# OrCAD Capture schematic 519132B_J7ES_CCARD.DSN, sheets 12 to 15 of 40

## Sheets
12 12. SOC MCU FLASH: size C
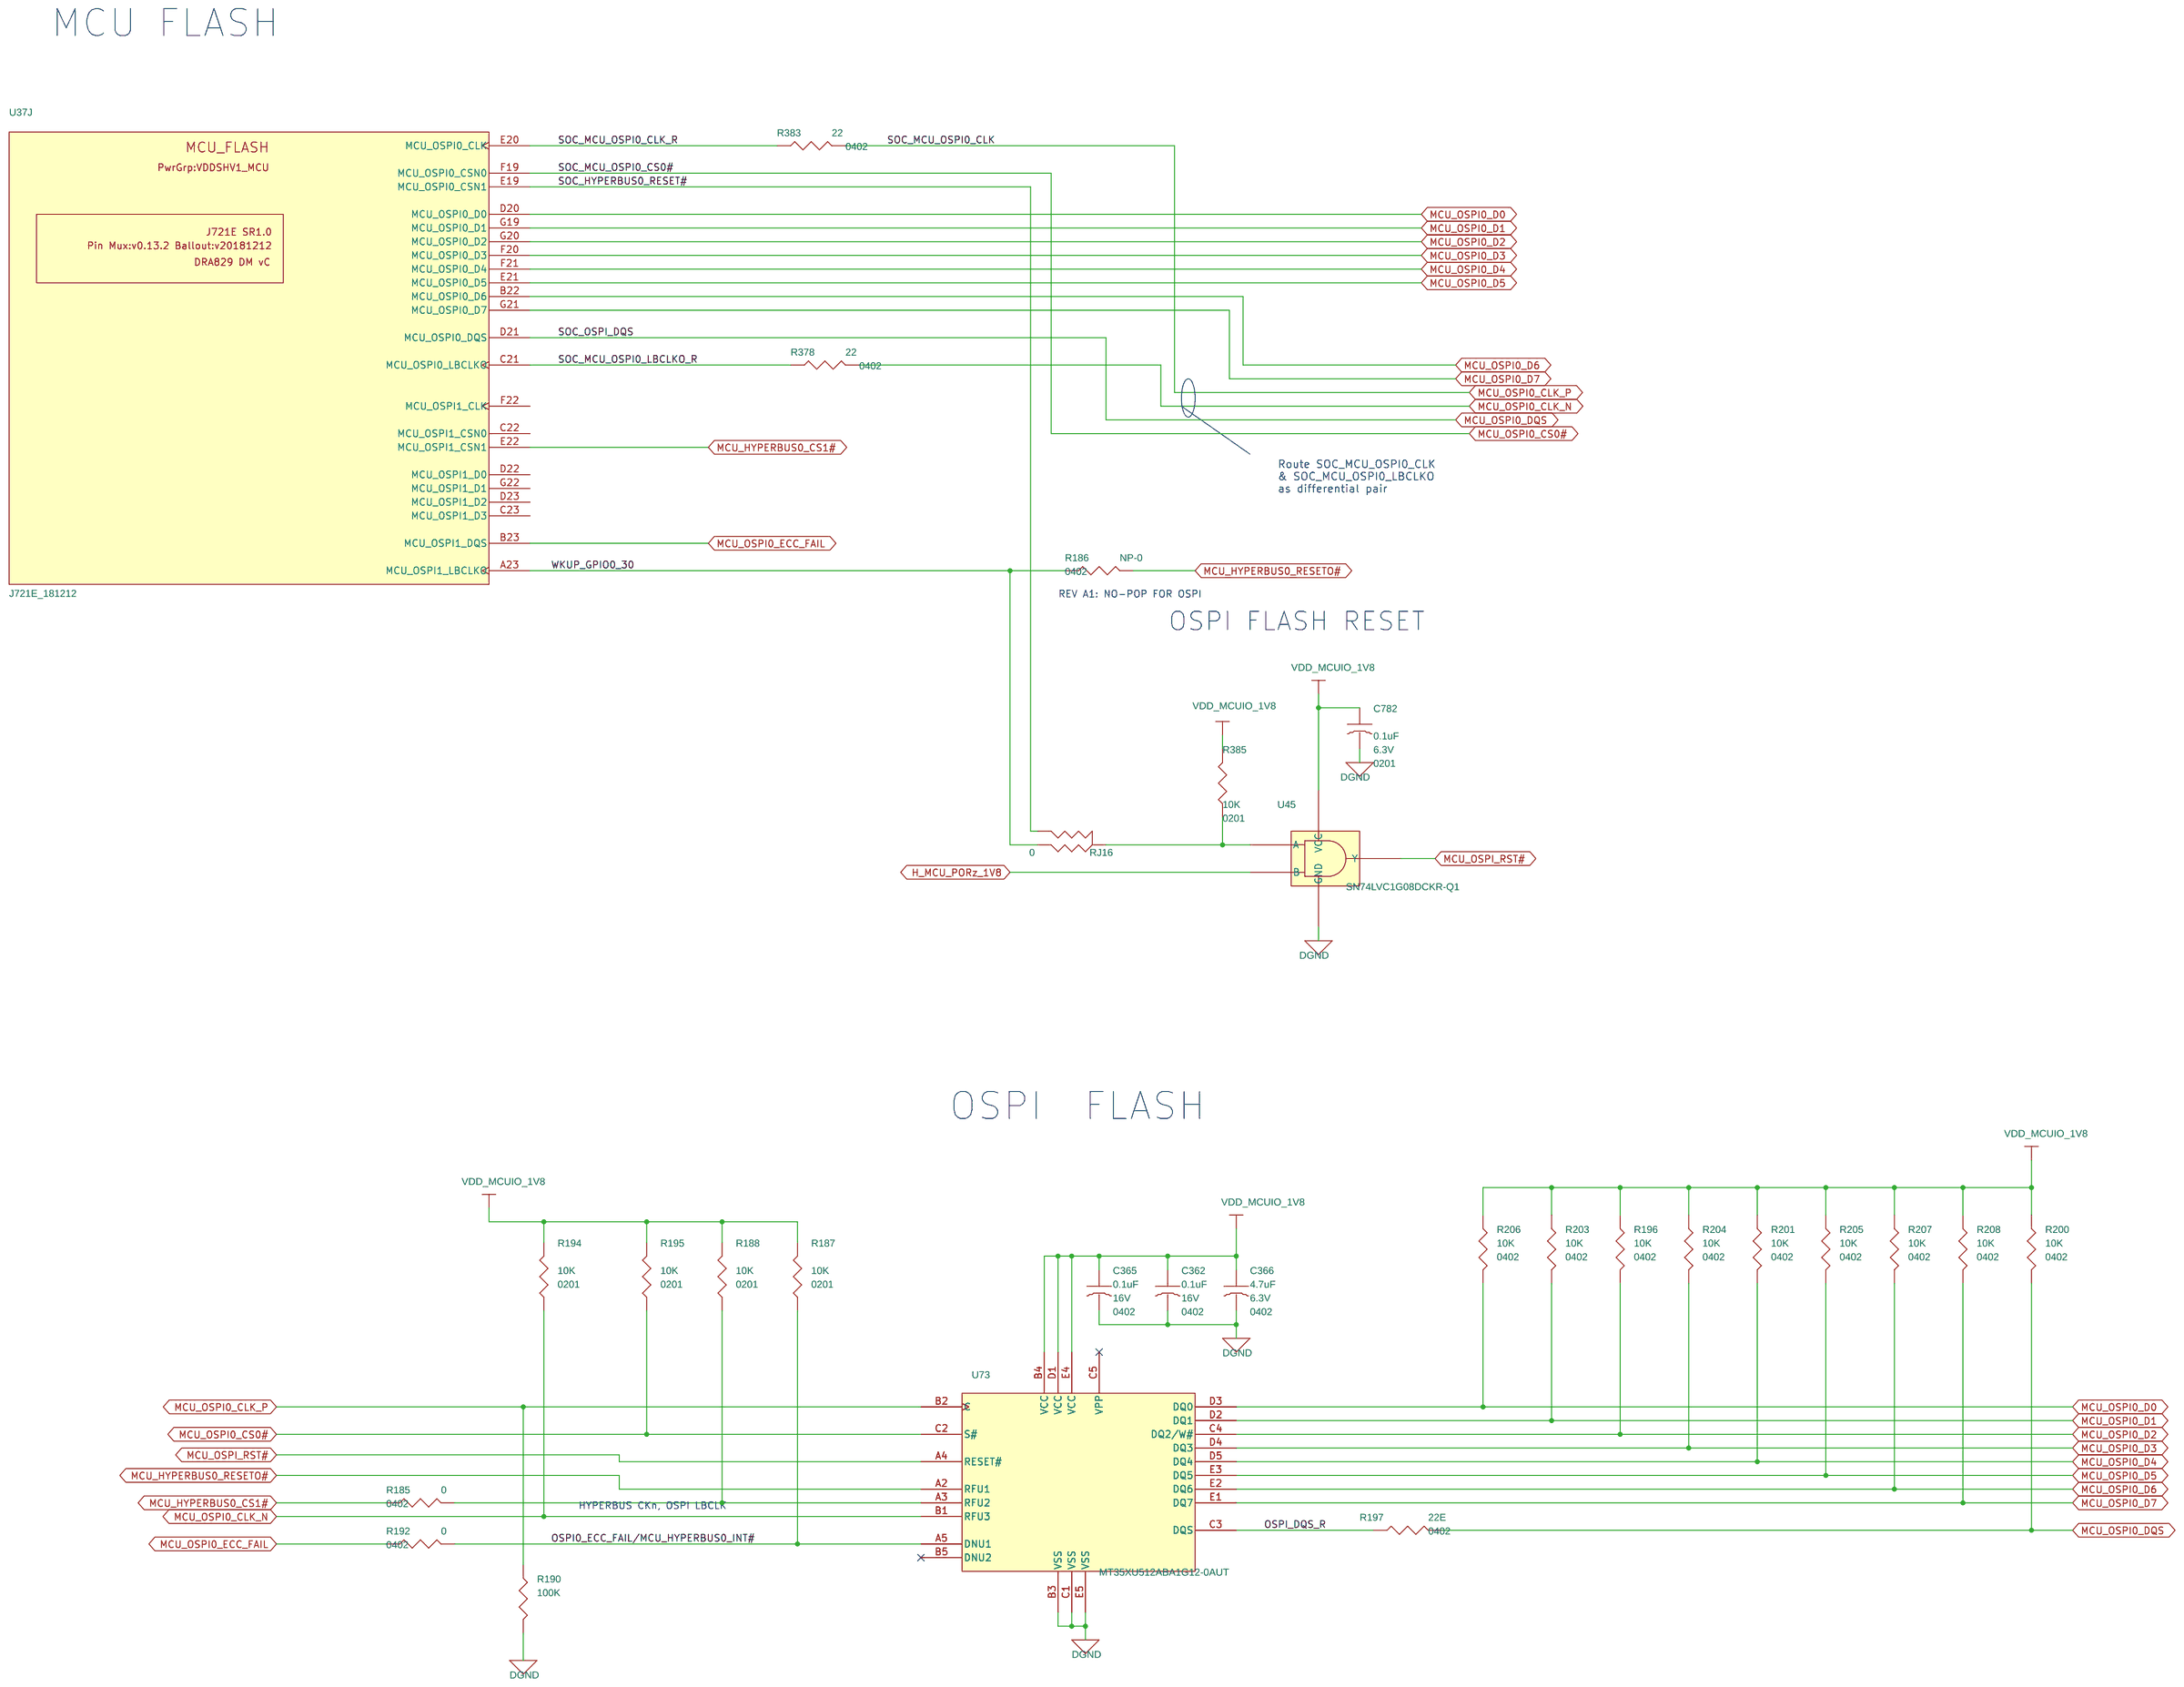
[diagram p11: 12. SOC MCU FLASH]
13 13. SOC RGMII, ADC: size C; rev: A
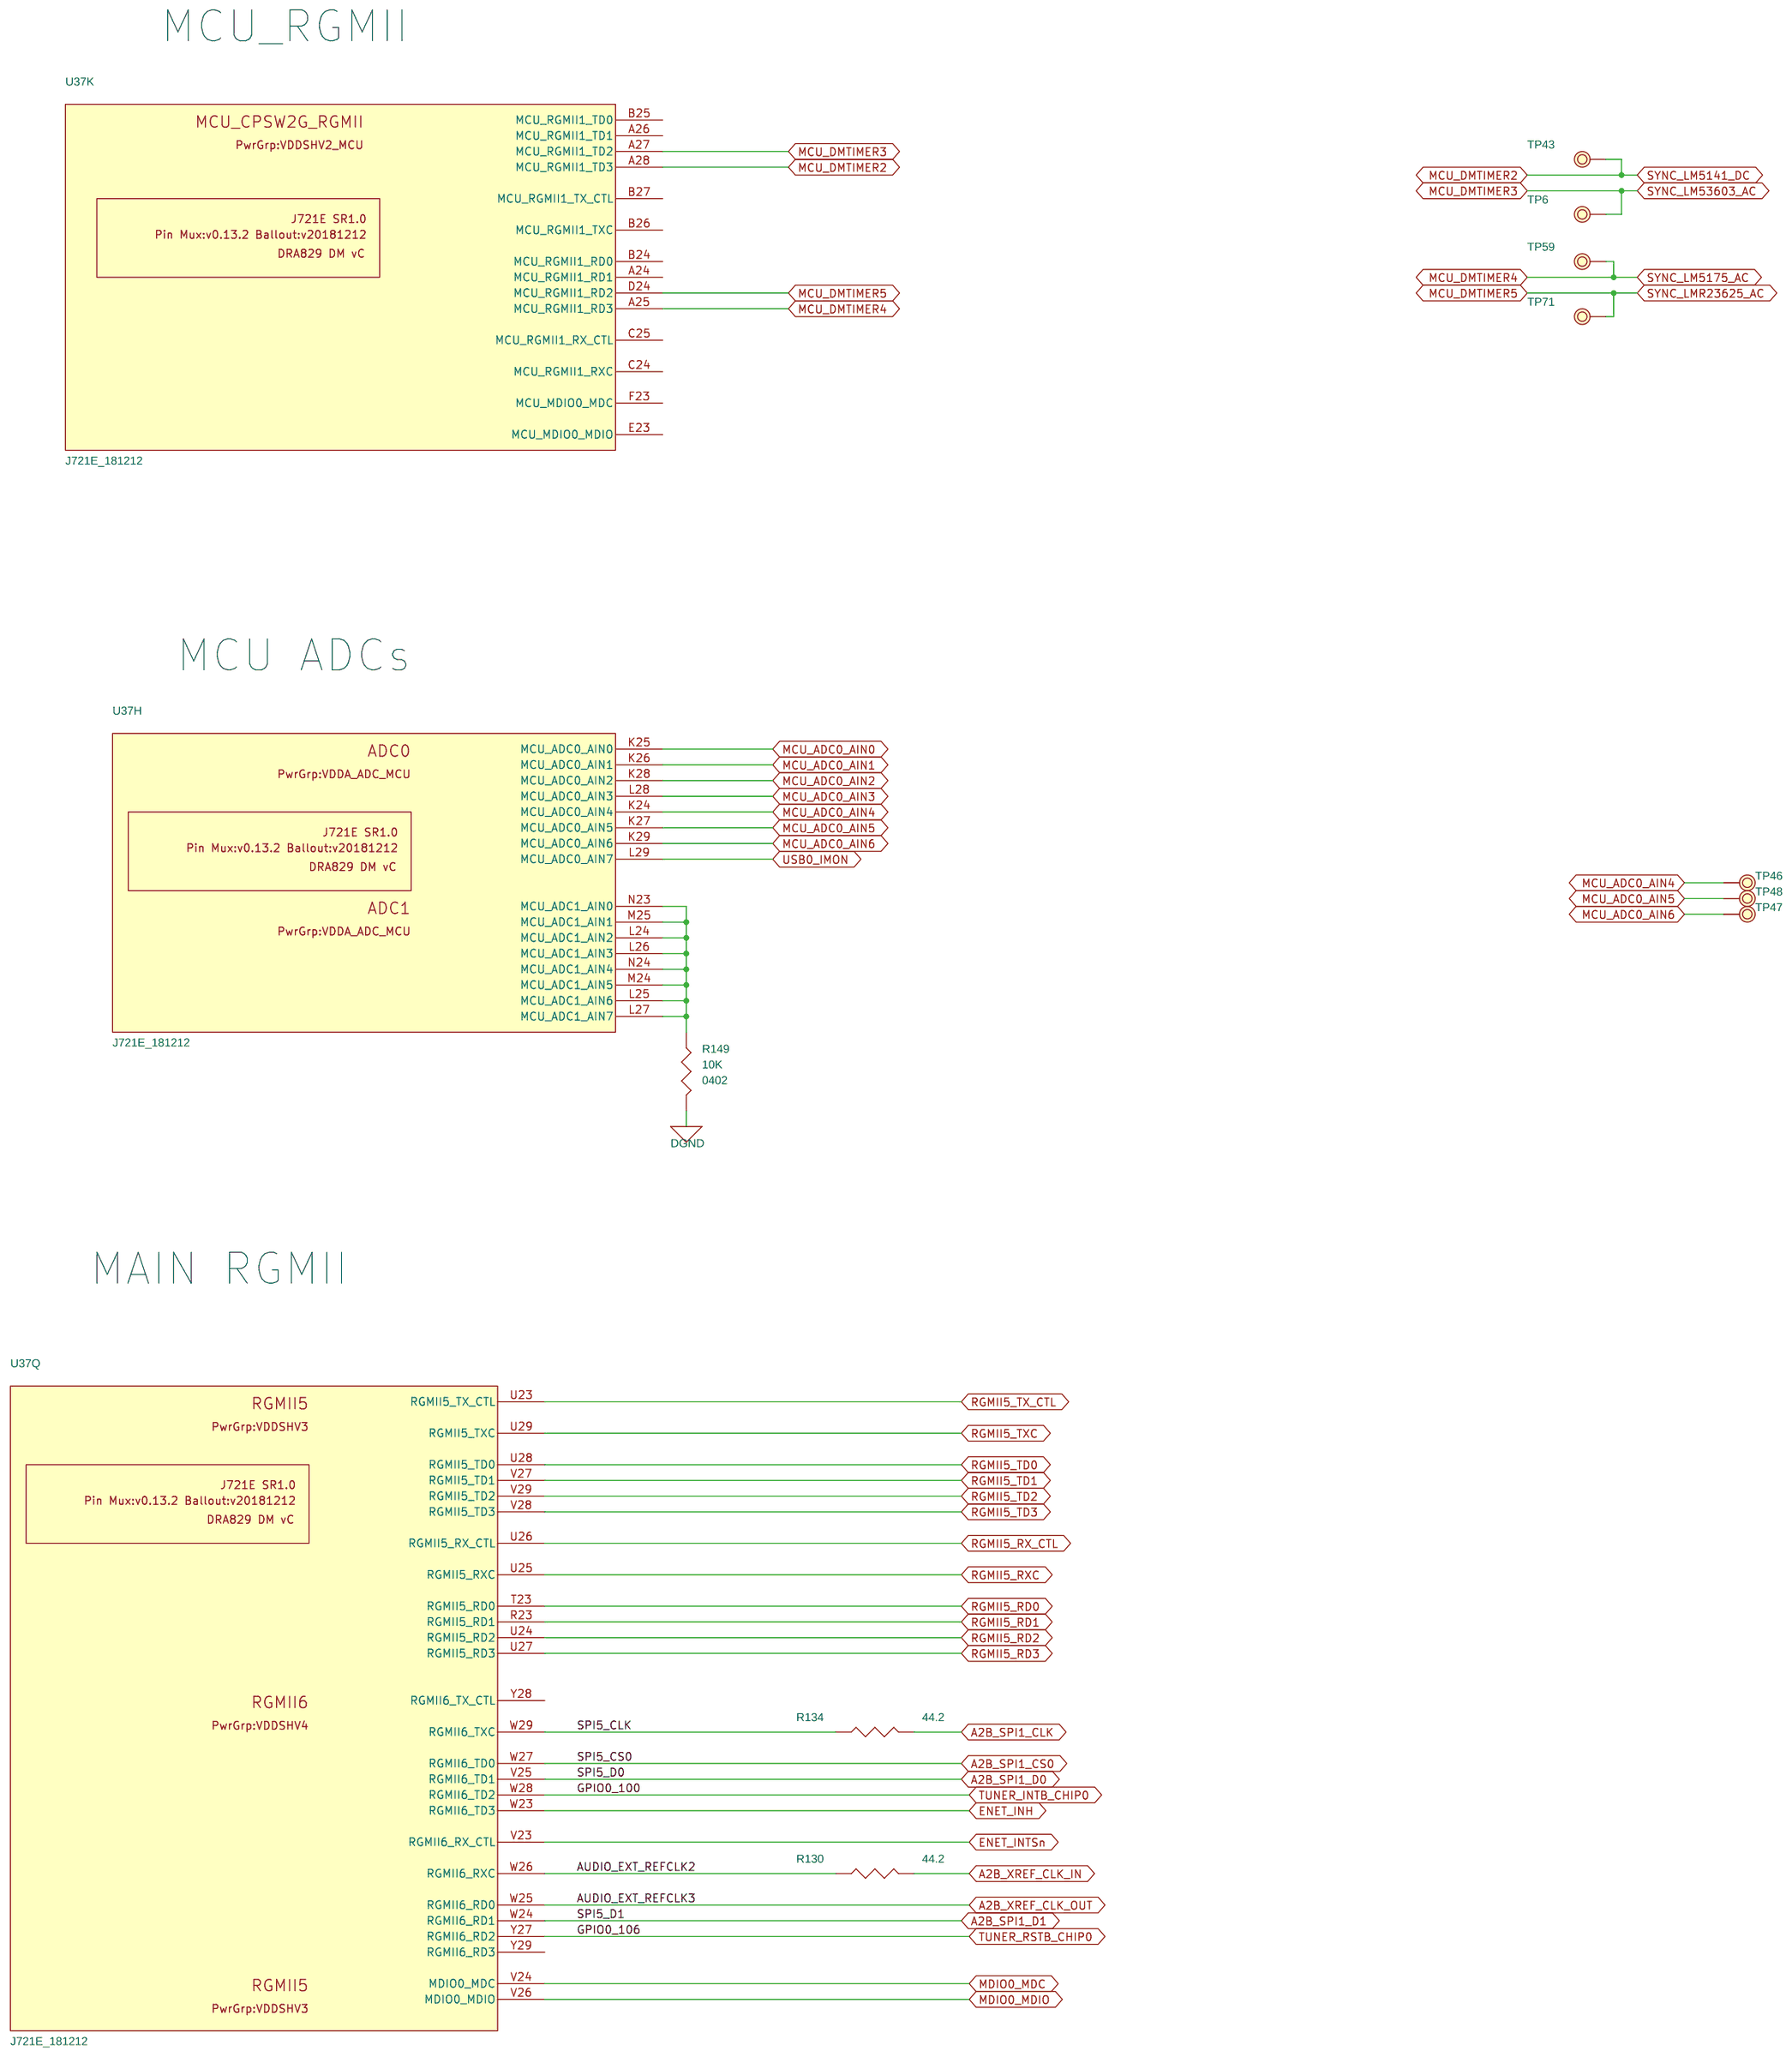
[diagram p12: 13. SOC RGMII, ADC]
14 14. SOC MCU & MAIN GEN IO, OSC: size C; rev: A
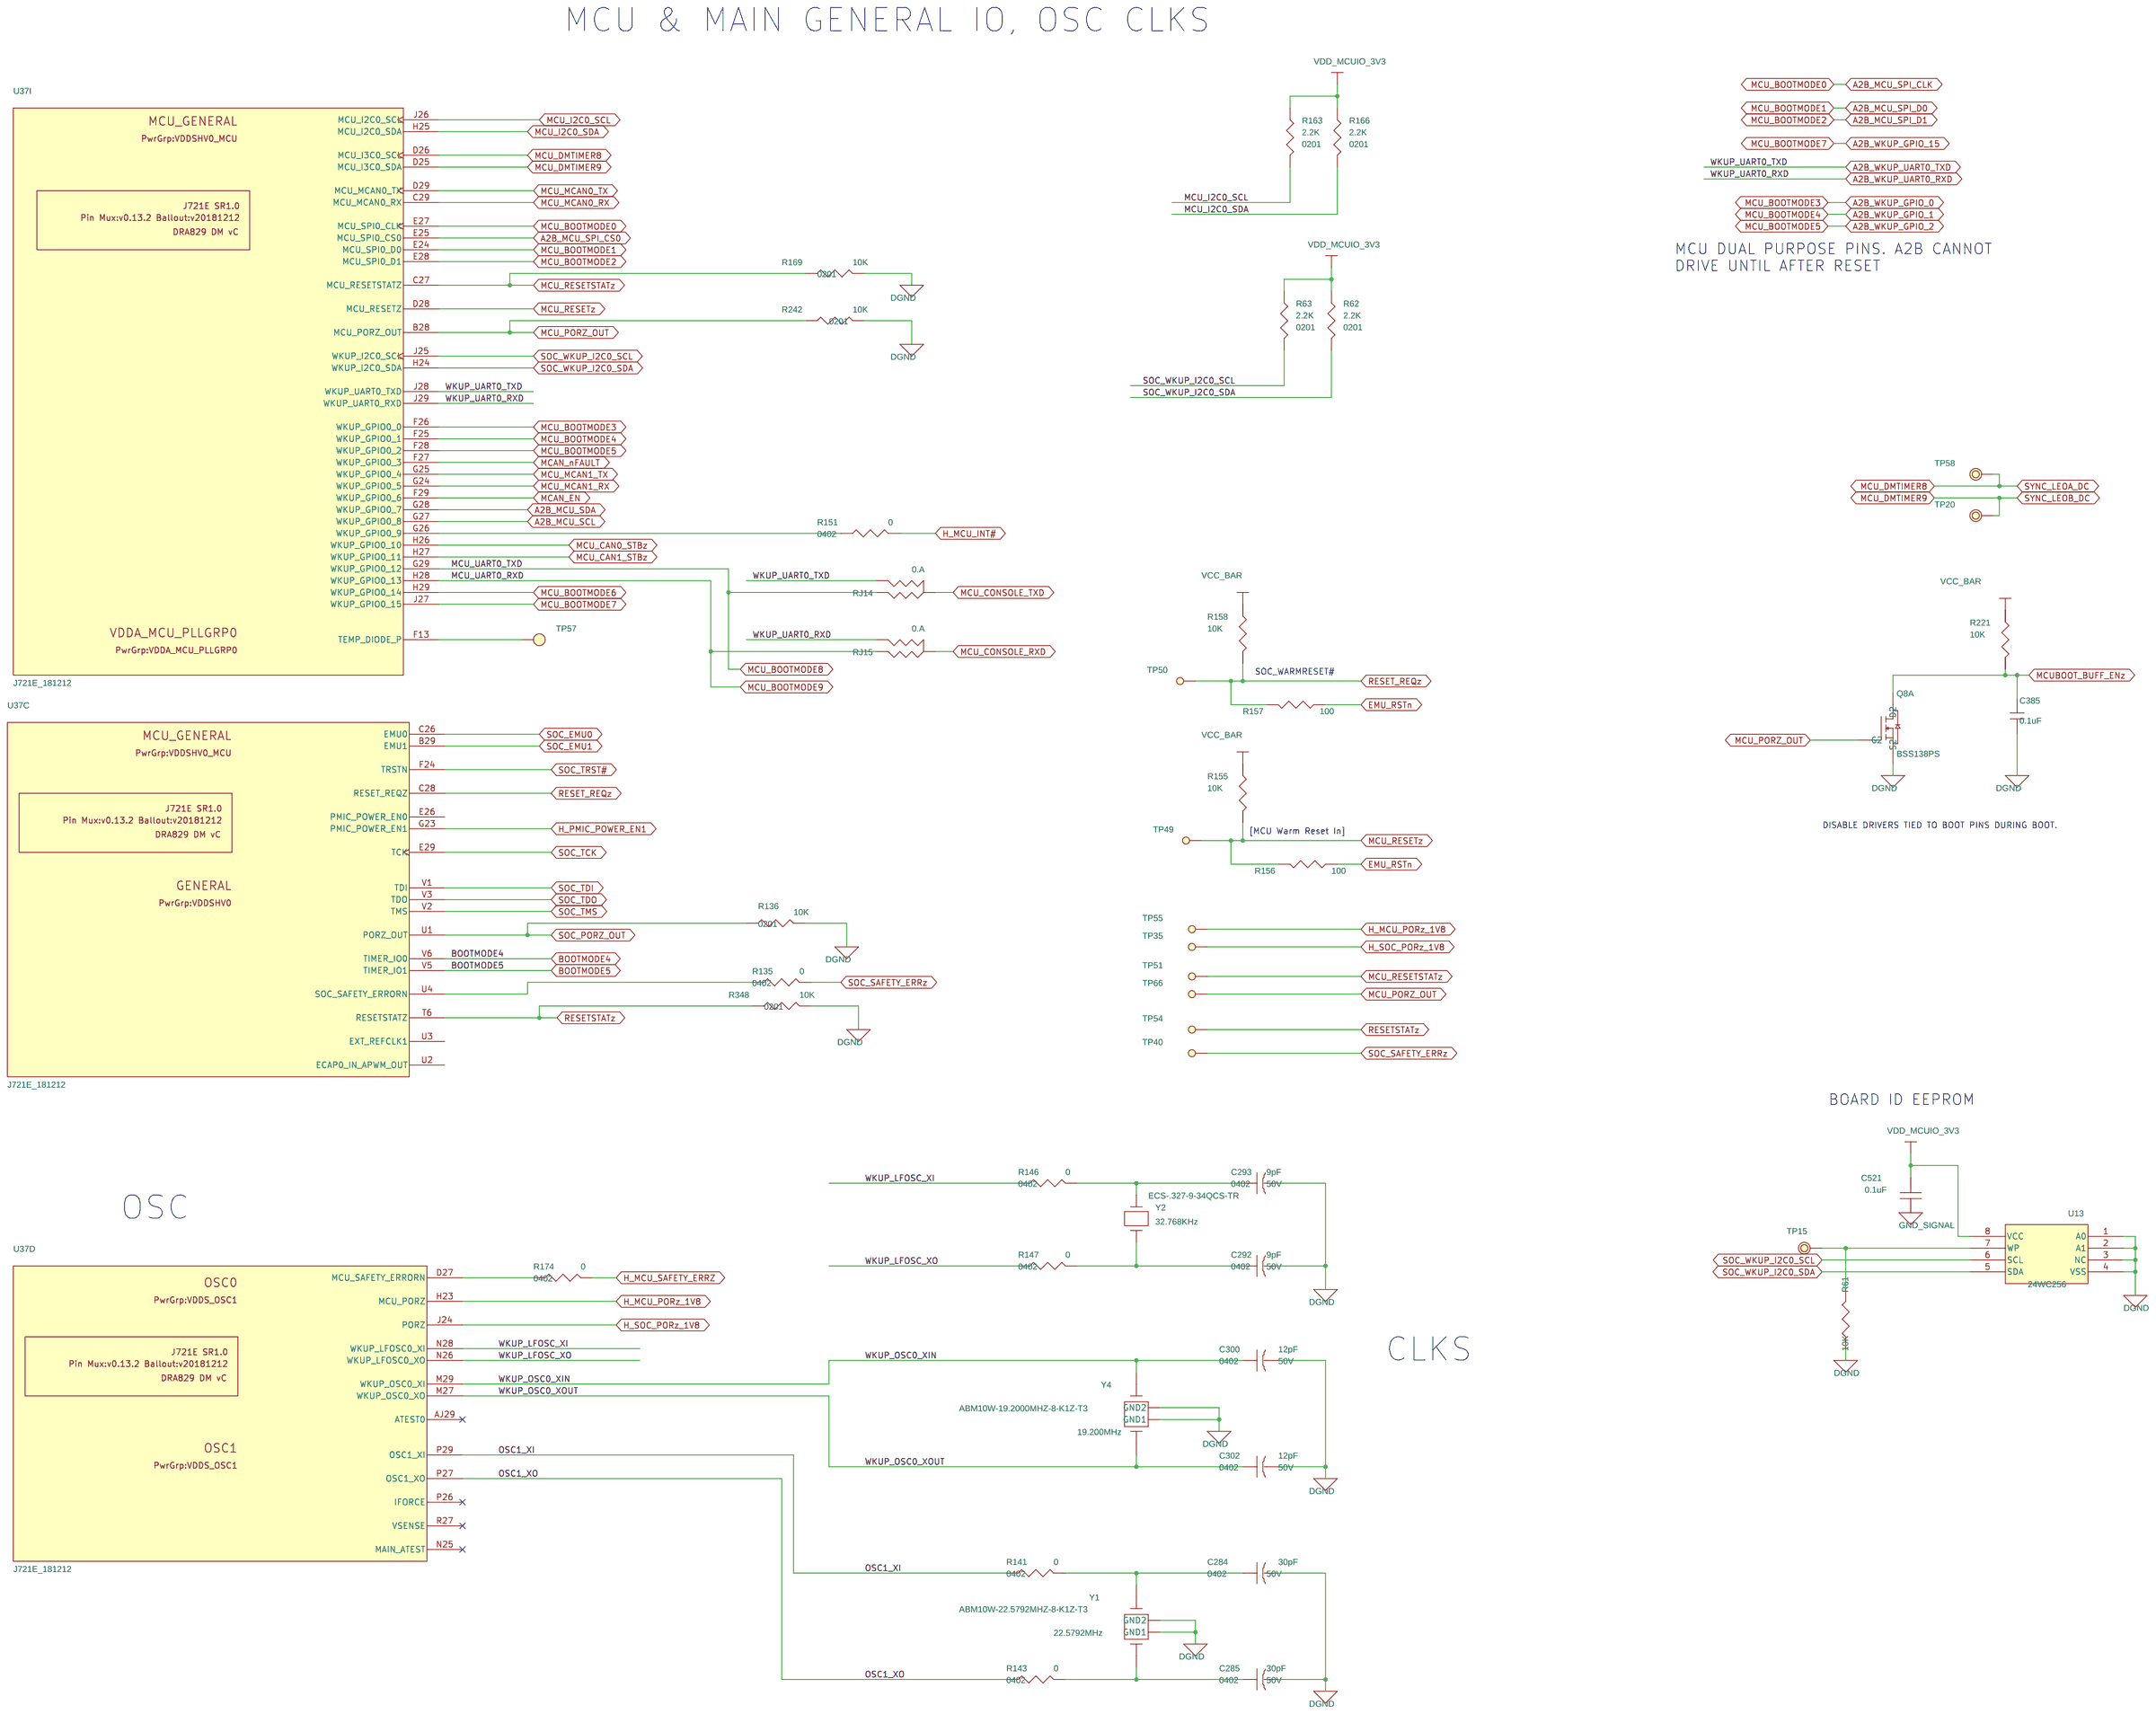
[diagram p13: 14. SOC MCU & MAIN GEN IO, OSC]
15 15. SOC GENERAL & USB: size C; rev: A
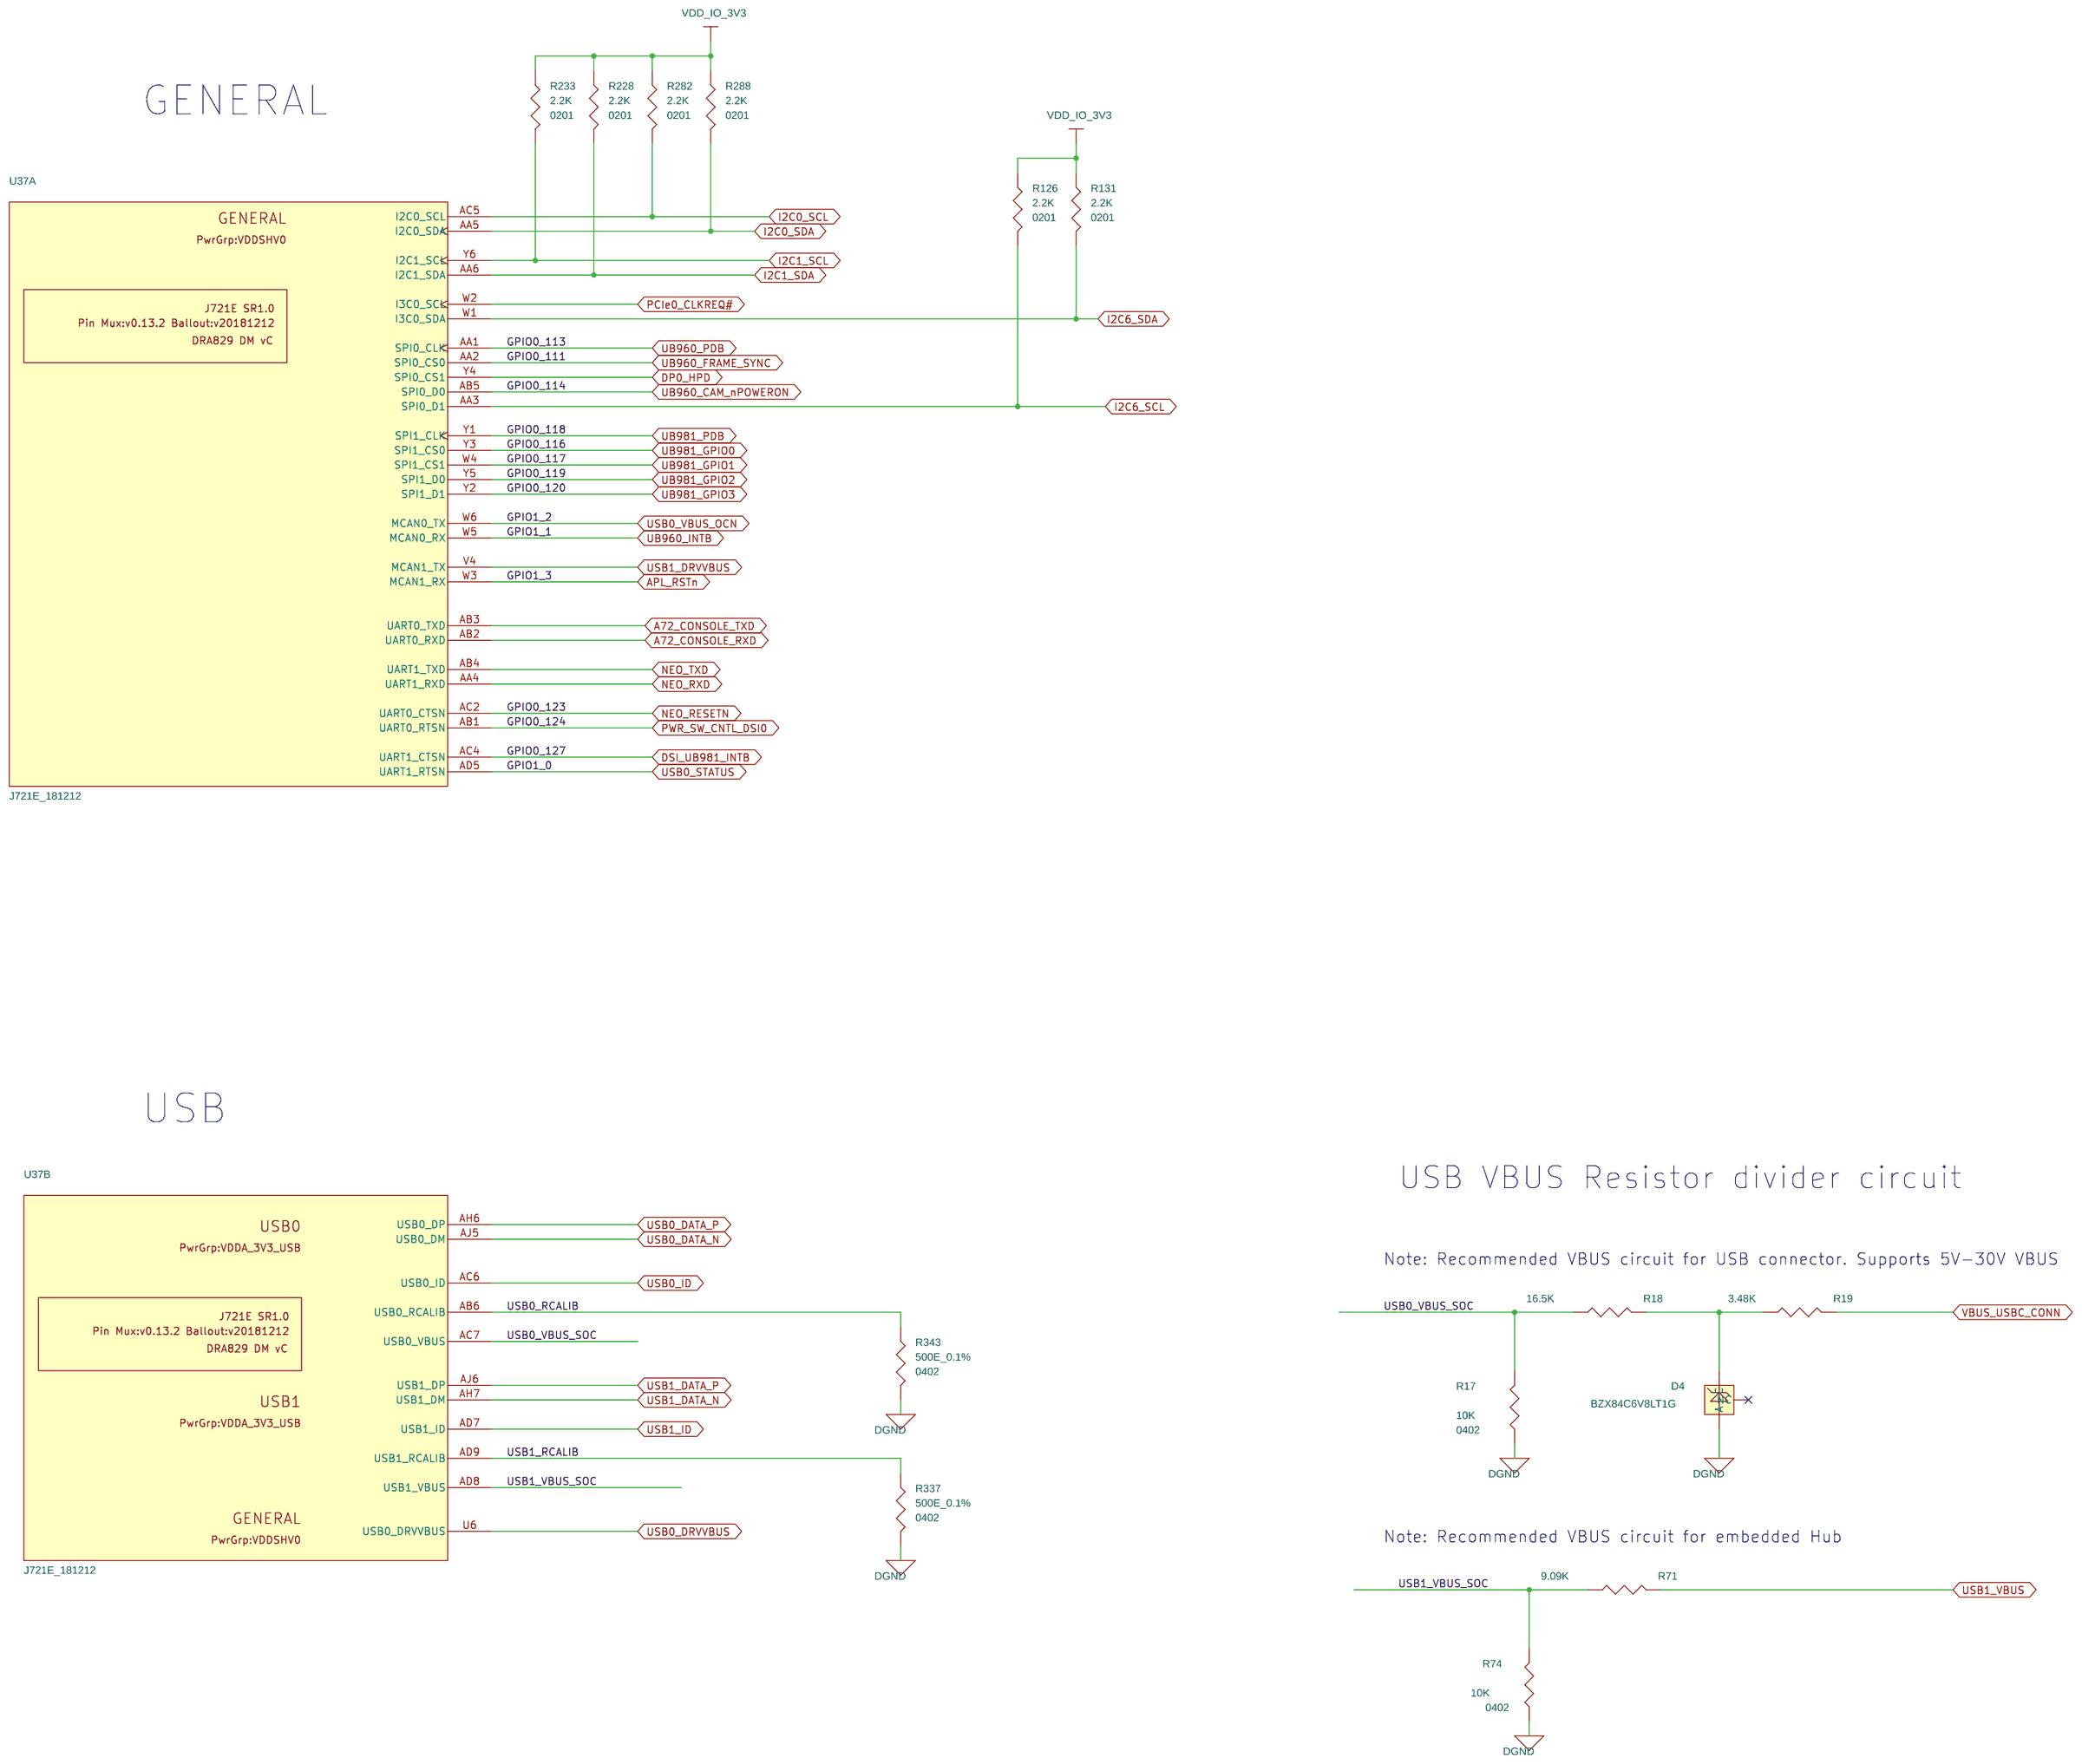
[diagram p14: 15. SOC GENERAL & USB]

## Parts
sheet 12. SOC MCU FLASH
C362  0.1uF  [c402-25]
C365  0.1uF  [c402-25]
C366  4.7uF  [c603-35x45]
C782  0.1uF  [c201-6p6spc]
R185  0  [r402-25]
R186  NP-0  [r402-25]
R187  10K  [r201-18p5x15]
R188  10K  [r201-18p5x15]
R190  100K  [r402-25]
R192  0  [r402-25]
R194  10K  [r201-18p5x15]
R195  10K  [r201-18p5x15]
R196  10K  [r402-25]
R197  22E  [r402-25]
R200  10K  [r402-25]
R201  10K  [r402-25]
R203  10K  [r402-25]
R204  10K  [r402-25]
R205  10K  [r402-25]
R206  10K  [r402-25]
R207  10K  [r402-25]
R208  10K  [r402-25]
R378  22  [r402-25]
R383  22  [r402-25]
R385  10K  [r201-18p5x15]
RJ16  0  [JMP402-25]
U45  SN74LVC1G08DCKR-Q1  [dck-5]
U73  MT35XU512ABA1G12-0AUT  [TPBGA24_39-37_240X320_1-2]
sheet 13. SOC RGMII, ADC
R130  44.2  [r201-18p5x15]
R134  44.2  [r201-18p5x15]
R149  10K  [r402-25]
TP6  TP  [tp-20RD10]
TP43  TP  [tp-20RD10]
TP46  TP  [tp-20RD10]
TP47  TP  [tp-20RD10]
TP48  TP  [tp-20RD10]
TP59  TP  [tp-20RD10]
TP71  TP  [tp-20RD10]
sheet 14. SOC MCU & MAIN GEN IO, OSC
C284  30pF  [c402-25]
C285  30pF  [c402-25]
C292  9pF  [c402-25]
C293  9pF  [c402-25]
C300  12pF  [c402-25]
C302  12pF  [c402-25]
C385  0.1uF  [c402-25]
C521  0.1uF  [c402-25]
Q8  BSS138PS  [sot363-16x45]  (sections A,B)
R61  10K  [r402-25]
R62  2.2K  [r201-18p5x15]
R63  2.2K  [r201-18p5x15]
R135  0  [r402-25]
R136  10K  [r201-18p5x15]
R141  0  [r402-25]
R143  0  [r402-25]
R146  0  [r402-25]
R147  0  [r402-25]
R151  0  [r402-25]
R155  10K  [r402-25]
R156  100  [r402-25]
R157  100  [r402-25]
R158  10K  [r402-25]
R163  2.2K  [r201-18p5x15]
R166  2.2K  [r201-18p5x15]
R169  10K  [r201-18p5x15]
R174  0  [r402-25]
R221  10K  [r402-25]
R242  10K  [r201-18p5x15]
R348  10K  [r201-18p5x15]
RJ14  0.A  [JMP402-25]
RJ15  0.A  [JMP402-25]
TP15  TP  [tp-30RD13]
TP20  TP  [tp-20RD10]
TP35  TP_VIA_MEM0  [tp-18RD8]
TP40  TP_VIA_MEM0  [tp-18RD8]
TP49  TP_VIA_MEM0  [tp-18RD8]
TP50  TP_VIA_MEM0  [tp-18RD8]
TP51  TP_VIA_MEM0  [tp-18RD8]
TP54  TP_VIA_MEM0  [tp-18RD8]
TP55  TP_VIA_MEM0  [tp-18RD8]
TP57  TP40_SMD  [TP40_SMD]
TP58  TP  [tp-20RD10]
TP66  TP_VIA_MEM0  [tp-18RD8]
U13  24WC256  [so8-25x75-295]
Y1  22.5792MHz  [XTAL4_S3225A_135X110_SMD_0-8]
Y2  32.768KHz  [XTAL_ECS-32_130X60_SMD_0-9]
Y4  19.200MHz  [XTAL4_ABM10W_100X80_SMD_0-6]
sheet 15. SOC GENERAL & USB
D4  BZX84C6V8LT1G  [SOT23-123_1-2]
R17  10K  [r402-25]
R18  16.5K  [r402-25]
R19  3.48K  [r402-25]
R71  9.09K  [r402-25]
R74  10K  [r402-25]
R126  2.2K  [r201-18p5x15]
R131  2.2K  [r201-18p5x15]
R228  2.2K  [r201-18p5x15]
R233  2.2K  [r201-18p5x15]
R282  2.2K  [r201-18p5x15]
R288  2.2K  [r201-18p5x15]
R337  500E_0.1%  [r402-25]
R343  500E_0.1%  [r402-25]
sheet 16. SOC PRG0 & PRG1
U37  J721E_181212  [FCBGA827_31-49_950X950_2-8]  (sections A,B,C,D,E,F,G,H,I,J,K,L,M,N,O,P,Q,R,S,T,U,V,W)

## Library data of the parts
C362 C365 = CAP: CAP CERAMIC 0.1uF 16V 5% X7R AUTO 0402; Chkd/date: MANIRAJA/241018; Crtd /date: ALVY/241018; Custom_Duty: 15%; Customs_HS_Code: 85322990; Distributor_name: DIGIKEY; Distributor_part_number: 490-16433-1-ND; Footprint Path: Y:\MIS_DATABASE\Library\ALTIUM_TOOL\PCB_FOOTPRINTS\Altium_Footprint_Lib.PcbLib; Height: 0.55MM; Library Path: Y:\MIS_DATABASE\Library\ALTIUM_TOOL\SCHEMATICS_PARTS\MS_DISCRETE_Library.schlib; Mfr_name: MURATA; Mfr_part_number: GCM155R71C104JA55D; Mistral Part No: 120018100055-R; Package: 0402; Part #: 104446-1100R; Part_type: CAPACITORS\CERAMIC; Project: TI_J7ES_EVM_CP; RoHS: RoHS; Temperature: -55°C+125°C; Tolerance: 5%; Voltage: 16V; Wattage: NA; Weight: 6mg; Datasheet: Y:\MIS_DATABASE\DATASHEETS\CAPACITORS\GCM155R71C104JA55D.PDF
C366 = CAP: CAP CERAMIC 4.7uF 6.3V 20% X6S 0402; Chkd/date: MANIRAJA/070319; Crtd /date: ALVY/070319; Custom_Duty: 15%; Customs_HS_Code: 85322990; Distributor_name: DIGIKEY; Distributor_part_number: 490-14458-1-ND; Footprint Path: Y:\MIS_DATABASE\Library\ALTIUM_TOOL\PCB_FOOTPRINTS\Altium_Footprint_Lib.PcbLib; Footprint Ref: c402-25; Height: 0.65MM; Library Path: Y:\MIS_DATABASE\Library\ALTIUM_TOOL\SCHEMATICS_PARTS\MS_DISCRETE_Library.schlib; MECHANICAL 3D STEP FILE: c402-25; Mfr_name: MURATA; Mfr_part_number: GRM155C80J475MEAAD; Mistral Part No: 120019030001-R; Package: 0402; Part #: 104938-0470R; Part_type: CAPACITORS\CERAMIC; Project: TI_J7ES_EVM_SOM; RoHS: RoHS; Temperature: -55°C+105°C; Tolerance: 20%; Voltage: 6.3V; Wattage: NA; Weight: 6mg; Datasheet: Y:\MIS_DATABASE\DATASHEETS\CAPACITORS\GRM155C80J475MEAAD.PDF
C782 = CAP: CAP CERAMIC 0.1uF 6.3V 10% X7S AUTO 0201; Chkd/date: MANIRAJA/011018; Crtd /date: MANIRAJA/011018; Custom_Duty: 15%; Customs_HS_Code: 85322990; Distributor_name: NA; Distributor_part_number: NA; Footprint Path: Y:\MIS_DATABASE\Library\ALTIUM_TOOL\PCB_FOOTPRINTS\Altium_Footprint_Lib.PcbLib; Height: 0.33MM; Library Path: Y:\MIS_DATABASE\Library\ALTIUM_TOOL\SCHEMATICS_PARTS\MS_DISCRETE_Library.schlib; Mfr_name: MURATA; Mfr_part_number: GCM033C70J104K; Mistral Part No: 120018100001-R; Package: 0201; Part #: 105047-1100R; Part_type: CAPACITORS\CERAMIC; Project: TI_J7_SVB-DUT; RoHS: RoHS; Temperature: -55°C+125°C; Tolerance: 10%; Voltage: 6.3V; Wattage: NA; Weight: NA; Datasheet: Y:\MIS_DATABASE\DATASHEETS\CAPACITORS\GCM033C70J104K.PDF
R135 R141 R143 R146 R147 R151 R174 R185 = RESISTOR: RES 0E 1/10W JUMPER 0402; Chkd/date: VASANTHA/061216; Crtd /date: NAVEED/201014; Custom_Duty: 15%; Customs_HS_Code: 85332119; Distributor_name: DIGIKEY; Distributor_part_number: P0.0JCT-ND; Footprint Path: Y:\MIS_DATABASE\Library\ALTIUM_TOOL\PCB_FOOTPRINTS\Altium_Footprint_Lib.PcbLib; Height: 0.40MM; IBISSP_MODLES: VALUE REPEATING 2 TIME; Library Path: Y:\MIS_DATABASE\Library\ALTIUM_TOOL\SCHEMATICS_PARTS\MS_DISCRETE_Library.schlib; Mfr_name: PANASONIC-ECG; Mfr_part_number: ERJ-2GE0R00X; Mistral Part No: 110018030052-R; Package: 0402; Part #: 101370-0001R; Part_type: RESISTORS\FIXED; Project: AEGIS POM; RoHS: RoHS; Temperature: -55°C+155°C; Tolerance: NA; Voltage: NA; Wattage: 1/10W; Weight: 0.8mg; Datasheet: Y:\MIS_DATABASE\DATASHEETS\RESISTORS\PAN-ERJSER_NOV17.PDF
R186 = RESISTOR: RES 0E 1/10W JUMPER 0402; Chkd/date: VASANTHA/061216; Crtd /date: NAVEED/201014; Custom_Duty: 15%; Customs_HS_Code: 85332119; Distributor_name: DIGIKEY; Distributor_part_number: P0.0JCT-ND; Footprint Path: Y:\MIS_DATABASE\Library\ALTIUM_TOOL\PCB_FOOTPRINTS\Altium_Footprint_Lib.PcbLib; Height: 0.40MM; IBISSP_MODLES: VALUE REPEATING 2 TIME; Library Path: Y:\MIS_DATABASE\Library\ALTIUM_TOOL\SCHEMATICS_PARTS\MS_DISCRETE_Library.schlib; Mfr_name: PANASONIC-ECG; Mfr_part_number: ERJ-2GE0R00X; Mistral Part No: 110018030052-R; Package: 0402; Part #: R0402-NOPOP; Part_type: RESISTORS\FIXED; Project: AEGIS POM; RoHS: RoHS; Temperature: -55°C+155°C; Tolerance: NA; Voltage: NA; Wattage: 1/10W; Weight: 0.8mg; Datasheet: Y:\MIS_DATABASE\DATASHEETS\RESISTORS\PAN-ERJSER_NOV17.PDF
R136 R169 R187 R188 R194 R195 R242 R348 R385 = RESISTOR: RES 10K 1/20W 1% 0201; Chkd/date: MANIRAJA/080519; Crtd /date: ALVY/080519; Custom_Duty: 15%; Customs_HS_Code: 85332119; Distributor_name: DIGIKEY; Distributor_part_number: 1276-3670-1-ND; Footprint Path: Y:\MIS_DATABASE\Library\ALTIUM_TOOL\PCB_FOOTPRINTS\Altium_Footprint_Lib.PcbLib; Height: 0.26MM; Library Path: Y:\MIS_DATABASE\Library\ALTIUM_TOOL\SCHEMATICS_PARTS\MS_DISCRETE_Library.schlib; Mfr_name: SAMSUNG; Mfr_part_number: RC0603F103CS; Mistral Part No: 110011040018-R; Package: 0201; Part #: 103413-1003R; Part_type: RESISTORS\FIXED; Project: BRUKER_SD820_COMMONDO; RoHS: RoHS; Temperature: -55°C+125°C; Tolerance: 1%; Voltage: NA; Wattage: 1/20W; Weight: 0.15mg; Datasheet: Y:\MIS_DATABASE\DATASHEETS\RESISTORS\SAMSUNG_RC-SER.PDF
R190 = RESISTOR: RES 100K 1/10W 5% 0402; Chkd/date: VASANTHA/291216; Crtd /date: GEETHA/190406; Custom_Duty: 15%; Customs_HS_Code: 85332119; Distributor_name: DIGIKEY; Distributor_part_number: P100KJCT-ND; Footprint Path: Y:\MIS_DATABASE\Library\ALTIUM_TOOL\PCB_FOOTPRINTS\Altium_Footprint_Lib.PcbLib; Height: 0.40MM; Library Path: Y:\MIS_DATABASE\Library\ALTIUM_TOOL\SCHEMATICS_PARTS\MS_DISCRETE_Library.schlib; Mfr_name: PANASONIC-ECG; Mfr_part_number: ERJ-2GEJ104X; Mistral Part No: 110009030177-R; Package: 0402; Part #: 102145-1004R; Part_type: RESISTORS\FIXED; Project: RED EYE; RoHS: RoHS; Temperature: -55°C+155°C; Tolerance: 5%; Voltage: NA; Wattage: 1/10W; Weight: 0.8mg; Datasheet: Y:\MIS_DATABASE\DATASHEETS\RESISTORS\PAN-ERJSER_NOV17.PDF
R192 = RESISTOR: RES 0E 1/10W JUMPER 0402; Assembly_Instruction: DNI; Chkd/date: VASANTHA/061216; Crtd /date: NAVEED/201014; Custom_Duty: 15%; Customs_HS_Code: 85332119; Distributor_name: DIGIKEY; Distributor_part_number: P0.0JCT-ND; Footprint Path: Y:\MIS_DATABASE\Library\ALTIUM_TOOL\PCB_FOOTPRINTS\Altium_Footprint_Lib.PcbLib; Height: 0.40MM; IBISSP_MODLES: VALUE REPEATING 2 TIME; Library Path: Y:\MIS_DATABASE\Library\ALTIUM_TOOL\SCHEMATICS_PARTS\MS_DISCRETE_Library.schlib; Mfr_name: PANASONIC-ECG; Mfr_part_number: ERJ-2GE0R00X; Mistral Part No: 110018030052-R; Package: 0402; Part #: 101370-0001R; Part_type: RESISTORS\FIXED; Project: AEGIS POM; RoHS: RoHS; Temperature: -55°C+155°C; Tolerance: NA; Voltage: NA; Wattage: 1/10W; Weight: 0.8mg; Datasheet: Y:\MIS_DATABASE\DATASHEETS\RESISTORS\PAN-ERJSER_NOV17.PDF
R17 R74 R196 = RESISTOR: RES 10K 1/16W 1% 0402; Chkd/date: VASANTHA/201216; Crtd /date: GEETHA/290506; Custom_Duty: 15%; Customs_HS_Code: 85332119; Distributor_name: DIGIKEY; Distributor_part_number: 311-10.0KLRTR-ND; Footprint Path: Y:\MIS_DATABASE\Library\ALTIUM_TOOL\PCB_FOOTPRINTS\Altium_Footprint_Lib.PcbLib; Height: 0.40MM; Library Path: Y:\MIS_DATABASE\Library\ALTIUM_TOOL\SCHEMATICS_PARTS\MS_DISCRETE_Library.schlib; Mfr_name: YAGEO AMERICA; Mfr_part_number: RC0402FR-0710KL; Mistral Part No: 110015090015-R; Package: 0402; Part #: 102145-1003R; Part_type: RESISTORS\FIXED; Project: VOCERA; RoHS: RoHS; Temperature: -55°C+155°C; Tolerance: 1%; Voltage: NA; Wattage: 1/16W; Weight: 0.65mg; Datasheet: Y:\MIS_DATABASE\DATASHEETS\RESISTORS\RCXXXXL-SER_MAR18.PDF
R197 R378 R383 = RESISTOR: RES 22E 1/16W 1% 0402; Chkd/date: SUHAS/290910; Crtd /date: MAZHAR/090909; Cust_part_number: 4700-80047E; Custom_Duty: 15%; Customs_HS_Code: 85332119; Distributor_name: DIGIKEY; Distributor_part_number: 311-22.0LRCT-ND; Footprint Path: Y:\MIS_DATABASE\Library\ALTIUM_TOOL\PCB_FOOTPRINTS\Altium_Footprint_Lib.PcbLib; Height: 0.40MM; Library Path: Y:\MIS_DATABASE\Library\ALTIUM_TOOL\SCHEMATICS_PARTS\MS_DISCRETE_Library.schlib; Mfr_name: YAGEO AMERICA; Mfr_part_number: RC0402FR-0722RL; Mistral Part No: 110009090004-R; Package: 0402; Part #: 102145-2210R; Part_type: RESISTORS\FIXED; Project: VMEFMCD; RoHS: RoHS; Temperature: -55°C+155°C; Tolerance: 1%; Voltage: NA; Wattage: 1/16W; Weight: 0.65mg; Datasheet: Y:\MIS_DATABASE\DATASHEETS\RESISTORS\RCXXXXL-SER_MAR18.PDF
R149 R200 R201 R203-R208 = RESISTOR: RES 10K 1/16W 1% 0402; Assembly_Instruction: DNI; Chkd/date: VASANTHA/201216; Crtd /date: GEETHA/290506; Custom_Duty: 15%; Customs_HS_Code: 85332119; Distributor_name: DIGIKEY; Distributor_part_number: 311-10.0KLRTR-ND; Footprint Path: Y:\MIS_DATABASE\Library\ALTIUM_TOOL\PCB_FOOTPRINTS\Altium_Footprint_Lib.PcbLib; Height: 0.40MM; Library Path: Y:\MIS_DATABASE\Library\ALTIUM_TOOL\SCHEMATICS_PARTS\MS_DISCRETE_Library.schlib; Mfr_name: YAGEO AMERICA; Mfr_part_number: RC0402FR-0710KL; Mistral Part No: 110015090015-R; Package: 0402; Part #: 102145-1003R; Part_type: RESISTORS\FIXED; Project: VOCERA; RoHS: RoHS; Temperature: -55°C+155°C; Tolerance: 1%; Voltage: NA; Wattage: 1/16W; Weight: 0.65mg; Datasheet: Y:\MIS_DATABASE\DATASHEETS\RESISTORS\RCXXXXL-SER_MAR18.PDF
RJ14-RJ16 = RJUMP3: Part #: 101370-0001R
U45 = SN74LVC1G08DBVRE4_SOT23-5: IC SINGLE 2-INPUT POSITIVE AND GATE SOT23-5; Chkd/date: SUHAS/221010; Crtd /date: USMAN/151008; Custom_Duty: 15%; Customs_HS_Code: 85423100; Distributor_name: DIGIKEY; Distributor_part_number: SN74LVC1G08DBVRE4-ND; Height: 1.45MM; Mfr_name: TEXAS INSTRUMENTS; Mfr_part_number: SN74LVC1G08DCKR; Mistral Part No: 141009060026-R; Package: DCK5; Part #: 101057-0008R; Part_type: ICS\DIGITAL\GATES; Project: KHAN_MAIN; RoHS: Sb/ Br FREE; Temperature: -40°C+85°C; Datasheet: Y:\MIS_DATABASE\DATASHEETS\ICS\DIGITAL\GATES\SN74LVC1G08.PDF
U73 = MT35XU512ABA1G12_TPBGA24_0: IC 1.7-2V 512Mb AUTOMOTIVE XCCELA FLASH MEMORY TPBGA24; Chkd/date: VASANTHA/090419; Crtd /date: ALVY/090419; Custom_Duty: 15%; Customs_HS_Code: 85423100; Distributor_name: DIGIKEY; Distributor_part_number: MT35XU512ABA1G12-0AUT-ND; Footprint Path: Y:\MIS_DATABASE\Library\ALTIUM_TOOL\PCB_FOOTPRINTS\Altium_Footprint_Lib.PcbLib; Height: 1.20MM; Library Path: Y:\MIS_DATABASE\Library\ALTIUM_TOOL\SCHEMATICS_PARTS\MS_MISCMEMORY_Library.schlib; Library Ref: MT35XU512ABA1G12_TPBGA24; Mfr_name: MICRON; Mistral Part No: 141119040001-R; Package: TPBGA24; Part #: 105326-0001R; Part_type: ICS\DIGITAL\MEMORY; Project: J7ES_SOM_DUAL-LEO_PMIC; RoHS: RoHS; Temperature: -40°C+125°C; Tolerance: NA; Voltage: NA; Wattage: NA; Weight: NA; Datasheet: Y:\MIS_DATABASE\DATASHEETS\ICS\MEMORY\MT35XU5XX.PDF
R130 R134 = R_1: Part #: 103413-4420R
TP6 TP20 TP43 TP46-TP48 TP58 TP59 TP71 = TP-20RD10: Part #: TP-20RD10-NO-POP
C284 C285 = CAP: CAP CERAMIC 30pF 50V 5% C0G(NP0) 0402; Chkd/date: MANIRAJA/160519; Crtd /date: ALVY/160519; Custom_Duty: 15%; Customs_HS_Code: 85322990; Distributor_name: DIGIKEY; Distributor_part_number: 1276-1682-1-ND; Footprint Path: Y:\MIS_DATABASE\Library\ALTIUM_TOOL\PCB_FOOTPRINTS\Altium_Footprint_Lib.PcbLib; Height: 0.55MM; Library Path: Y:\MIS_DATABASE\Library\ALTIUM_TOOL\SCHEMATICS_PARTS\MS_DISCRETE_Library.schlib; Mfr_name: SAMSUNG; Mfr_part_number: CL05C300JB5NNNC; Mistral Part No: 120015010016-R; Package: 0402; Part #: 102756-1304R; Part_type: CAPACITORS\CERAMIC; Project: J7ES_SOM_DUAL-LEO_PMIC; RoHS: RoHS; Temperature: -55°C+125°C; Tolerance: 5%; Voltage: 50V; Wattage: NA; Weight: NA; Datasheet: Y:\MIS_DATABASE\DATASHEETS\CAPACITORS\CL05C300JB5NNNC.PDF
C292 C293 = CAP: CAP CERAMIC 9pF 50V 0.5pF% C0G(NP0) AUTO 0402; Chkd/date: VASANTHA/090419; Crtd /date: ALVY/090419; Custom_Duty: 15%; Customs_HS_Code: 85322990; Distributor_name: DIGIKEY; Distributor_part_number: 445-12155-1-ND; Footprint Path: Y:\MIS_DATABASE\Library\ALTIUM_TOOL\PCB_FOOTPRINTS\Altium_Footprint_Lib.PcbLib; Height: 0.55MM; Library Path: Y:\MIS_DATABASE\Library\ALTIUM_TOOL\SCHEMATICS_PARTS\MS_DISCRETE_Library.schlib; Mfr_name: TDK CORPORATION; Mfr_part_number: CGA2B2NP01H090D050BA; Mistral Part No: 120019040066-R; Package: 0402; Part #: 105319-1094R; Part_type: CAPACITORS\CERAMIC; Project: J7ES_SOM_DUAL-LEO_PMIC; RoHS: RoHS; Temperature: -55°C+150°C; Tolerance: 0.5pF%; Voltage: 50V; Wattage: NA; Weight: 0.65mg; Datasheet: Y:\MIS_DATABASE\DATASHEETS\CAPACITORS\CGA2B2NP01H090D050BA.PDF
C300 C302 = CAP: CAP CERAMIC 12pF 50V 5% C0G(NP0) 0402; Chkd/date: SHREESHAIL/281105; Crtd /date: MAZHAR/040505; Custom_Duty: 15%; Customs_HS_Code: 85322990; Distributor_name: DIGIKEY; Distributor_part_number: 478-1071-1-ND; Footprint Path: Y:\MIS_DATABASE\Library\ALTIUM_TOOL\PCB_FOOTPRINTS\Altium_Footprint_Lib.PcbLib; Height: 0.56MM; Library Path: Y:\MIS_DATABASE\Library\ALTIUM_TOOL\SCHEMATICS_PARTS\MS_DISCRETE_Library.schlib; Mfr_name: AVX CORPORATION; Mfr_part_number: 04025A120JAT2A; Mistral Part No: 120015110024-R; Package: 0402; Part #: 101782-1124R; Part_type: CAPACITORS\CERAMIC; Project: EPDA_CORE; RoHS: RoHS; Temperature: -55°C+125°C; Tolerance: 5%; Voltage: 50V; Wattage: NA; Weight: 0.65mg; Datasheet: Y:\MIS_DATABASE\DATASHEETS\CAPACITORS\AVX_MLC.PDF
C385 = Cap_100nF_Cermc_16V_10%_603_4: Part #: 104446-1100R; Voltage: 16V
C521 = CAP_.1_uF_10%_0603: Part #: 104446-1100R; Voltage: 16V
Q8 = BSS138PS: Part #: 104958-0001R
R61 = R_1: Part #: 102145-1003R
R62 R63 R163 R166 R228 R233 R282 R288 = RESISTOR: RES 2.2K 1/20W 5% 0201; Chkd/date: MANIRAJA/050517; Crtd /date: MANIRAJA/050517; Custom_Duty: 15%; Customs_HS_Code: 85332119; Distributor_name: DIGIKEY; Distributor_part_number: 311-2.2KNCT-ND; Footprint Path: Y:\MIS_DATABASE\Library\ALTIUM_TOOL\PCB_FOOTPRINTS\Altium_Footprint_Lib.PcbLib; Height: 0.26MM; Library Path: Y:\MIS_DATABASE\Library\ALTIUM_TOOL\SCHEMATICS_PARTS\MS_DISCRETE_Library.schlib; Mfr_name: YAGEO AMERICA; Mfr_part_number: RC0201JR-072K2L; Mistral Part No: 110009030427-R; Package: 0201; Part #: 103158-2202R; Part_type: RESISTORS\FIXED; Project: GOLDEN-I LITE; RoHS: RoHS; Temperature: -55°C+125°C; Tolerance: 5%; Voltage: NA; Wattage: 1/20W; Weight: 0.17mg; Datasheet: Y:\MIS_DATABASE\DATASHEETS\RESISTORS\RCXXXXL-SER_MAR18.PDF
R155 R158 R221 = R_0: Part #: 102145-1003R
R156 R157 = R: Part #: 102145-1001R
TP15 = TP-30RD13: Part #: TP-30RD13-NO-POP
TP35 TP40 TP49-TP51 TP54 TP55 TP66 = TP_VIA_MEM0_0: Part #: TP-18RD8-NO-POP
TP57 = TESTPOINT: TESTPOINT CIR 40 SMD; Chkd/date: MAZHAR/190505; Crtd /date: MAZHAR/190505; Distributor_name: NA; Distributor_part_number: NA; Footprint Path: Y:\MIS_DATABASE\Library\ALTIUM_TOOL\PCB_FOOTPRINTS\Altium_Footprint_Lib.PcbLib; Height: NA; Library Path: Y:\MIS_DATABASE\Library\ALTIUM_TOOL\SCHEMATICS_PARTS\MS_DISCRETE_Library.schlib; MECHANICAL 3D STEP FILE: NA; Mfr_name: LOCAL; Mistral Part No: 130009030933; Package: SMD; Part #: NOPOP; Project: RAINIER-3; RoHS: NA; Temperature: NA; Tolerance: NA; Voltage: NA; Wattage: NA; Weight: NA; Datasheet: NA
U13 = 24WC256: Part #: 102235-0001R
Y1 = CRY4_ABM8G: CRY 22.5792MHz 8pF SMD; Chkd/date: MANIRAJA/250119; Crtd /date: ALVY/250119; Custom_Duty: 24%; Customs_HS_Code: 85439000; Distributor_name: DIGIKEY; Distributor_part_number: ABM10W-22.5792MHZ-8-K1Z-T3-ND; Footprint Path: Y:\MIS_DATABASE\Library\ALTIUM_TOOL\PCB_FOOTPRINTS\Altium_Footprint_Lib.PcbLib; Footprint Ref: XTAL4_ABM10W_100X80_SMD_0-6; Height: 0.60MM; Library Path: Y:\MIS_DATABASE\Library\ALTIUM_TOOL\SCHEMATICS_PARTS\MS_DISCRETE_Library.schlib; MECHANICAL 3D STEP FILE: XTAL4_ABM10W_100X80_SMD_0-6; Mfr_name: ABRACON CORPORATION; Mfr_part_number: ABM10W-22.5792MHZ-8-K1Z-T3; Mistral Part No: 130019010010-R; Package: SMD; Part #: 105272-2257R; Part_type: CRYSTAL; Project: TI_J7_SVB-DUT; RoHS: RoHS; Temperature: -40°C+125°C; Tolerance: NA; Voltage: NA; Wattage: NA; Weight: NA; Datasheet: Y:\MIS_DATABASE\DATASHEETS\MISC\CRY_OSC\ABM10W.PDF
Y2 = CRY: CRY 32.768KHz 9pF SMD; Chkd/date: VASANTHA/090419; Crtd /date: ALVY/090419; Custom_Duty: 24%; Customs_HS_Code: 85439000; Distributor_name: DIGIKEY; Distributor_part_number: XC2160CT-ND; Footprint Path: Y:\MIS_DATABASE\Library\ALTIUM_TOOL\PCB_FOOTPRINTS\Altium_Footprint_Lib.PcbLib; Height: 0.90MM; Library Path: Y:\MIS_DATABASE\Library\ALTIUM_TOOL\SCHEMATICS_PARTS\MS_DISCRETE_Library.schlib; Mfr_name: ECS INC; Mfr_part_number: ECS-.327-9-34QCS-TR; Mistral Part No: 130019040003-R; Package: SMD; Part #: 105332-3276R; Part_type: CRYSTAL; Project: J7ES_SOM_DUAL-LEO_PMIC; RoHS: RoHS; Temperature: -40°C+125°C; Tolerance: NA; Voltage: NA; Wattage: NA; Weight: 16mg; Datasheet: Y:\MIS_DATABASE\DATASHEETS\MISC\CRY_OSC\ECS-34Q.PDF
Y4 = CRY4_ABM8G: CRY 19.200MHz 8pF SMD; Chkd/date: MANIRAJA/250119; Crtd /date: ALVY/250119; Custom_Duty: 24%; Customs_HS_Code: 85439000; Distributor_name: DIGIKEY; Distributor_part_number: ABM10W-19.2000MHZ-8-K1Z-T3-ND; Footprint Path: Y:\MIS_DATABASE\Library\ALTIUM_TOOL\PCB_FOOTPRINTS\Altium_Footprint_Lib.PcbLib; Height: 0.60MM; Library Path: Y:\MIS_DATABASE\Library\ALTIUM_TOOL\SCHEMATICS_PARTS\MS_DISCRETE_Library.schlib; Mfr_name: ABRACON CORPORATION; Mfr_part_number: ABM10W-19.2000MHZ-8-K1Z-T3; Mistral Part No: 130019010009-R; Package: SMD; Part #: 105273-1920R; Part_type: CRYSTAL; Project: TI_J7_SVB-DUT; RoHS: RoHS; Temperature: -40°C+125°C; Tolerance: NA; Voltage: NA; Wattage: NA; Weight: NA; Datasheet: Y:\MIS_DATABASE\DATASHEETS\MISC\CRY_OSC\ABM10W.PDF
D4 = DIODE_ZENER_SOT23_13: DIODE ZENER 250mW 6.8V SOT23-123; Chkd/date: MANIRAJA/031017; Crtd /date: MANIRAJA/031017; Custom_Duty: 15%; Customs_HS_Code: 85412900; Distributor_name: DIGIKEY; Distributor_part_number: BZX84C6V8LT1GOSCT-ND; Height: 1.11MM; Mfr_name: ON SEMICONDUCTOR; Mistral Part No: 130017100002-R; Package: SOT23-123; Part #: 105268-0068R; Part_type: DIODE\ZENER; Project: TI_MAXIE_CPB; RoHS: RoHS; Temperature: -65°C+150°C; Tolerance: NA; Voltage: 6.8V; Wattage: NA; Weight: 8mg; Datasheet: Y:\MIS_DATABASE\DATASHEETS\DISCRETES\DIODES\BZX84XX.PDF
R18 = RESISTOR: RES 16.5K 1/10W 1% 0402; Chkd/date: VASANTHA/291216; Crtd /date: MUDDU/080310; Custom_Duty: 15%; Customs_HS_Code: 85332119; Distributor_name: DIGIKEY; Distributor_part_number: P16.5KLCT-ND; Footprint Path: Y:\MIS_DATABASE\Library\ALTIUM_TOOL\PCB_FOOTPRINTS\Altium_Footprint_Lib.PcbLib; Height: 0.40MM; Library Path: Y:\MIS_DATABASE\Library\ALTIUM_TOOL\SCHEMATICS_PARTS\MS_DISCRETE_Library.schlib; Mfr_name: PANASONIC-ECG; Mfr_part_number: ERJ-2RKF1652X; Mistral Part No: 110010030024-R; Package: 0402; Part #: 102145-1653R; Part_type: RESISTORS\FIXED; Project: VME_DSP_SUITE; RoHS: RoHS; Temperature: -55°C+155°C; Tolerance: 1%; Voltage: NA; Wattage: 1/10W; Weight: 0.8mg; Datasheet: Y:\MIS_DATABASE\DATASHEETS\RESISTORS\PAN-ERJSER_NOV17.PDF
R19 = RESISTOR: RES 3.4K 1/10W 1% 0402; Chkd/date: USMAN/231211; Crtd /date: CHAITHANYA/231211; Custom_Duty: 15%; Customs_HS_Code: 85332119; Distributor_name: DIGIKEY; Distributor_part_number: P3.40KLCT-ND; Footprint Path: Y:\MIS_DATABASE\Library\ALTIUM_TOOL\PCB_FOOTPRINTS\Altium_Footprint_Lib.PcbLib; Height: 0.40MM; Library Path: Y:\MIS_DATABASE\Library\ALTIUM_TOOL\SCHEMATICS_PARTS\MS_DISCRETE_Library.schlib; Mfr_name: PANASONIC-ECG; Mfr_part_number: ERJ-2RKF3401X; Mistral Part No: 110011120023-R; Package: 0402; Part #: 102145-3482R; Part_type: RESISTORS\FIXED; Project: NA10NG; RoHS: RoHS; Temperature: -55°C+155°C; Tolerance: 1%; Voltage: NA; Wattage: 1/10W; Weight: 0.8mg; Datasheet: Y:\MIS_DATABASE\DATASHEETS\RESISTORS\PAN-ERJSER_NOV17.PDF
R71 = RESISTOR: RES 9.09K 1/16W 1% 0402; Chkd/date: VASANTHA/281216; Crtd /date: BAVISH/010611; Custom_Duty: 15%; Customs_HS_Code: 85332119; Distributor_name: DIGIKEY; Distributor_part_number: 541-9.09KLCT-ND; Footprint Path: Y:\MIS_DATABASE\Library\ALTIUM_TOOL\PCB_FOOTPRINTS\Altium_Footprint_Lib.PcbLib; Height: 0.40MM; Library Path: Y:\MIS_DATABASE\Library\ALTIUM_TOOL\SCHEMATICS_PARTS\MS_DISCRETE_Library.schlib; Mfr_name: VISHAY; Mfr_part_number: CRCW04029K09FKED; Mistral Part No: 110011060006-R; Package: 0402; Part #: 102145-9092R; Part_type: RESISTORS\FIXED; Project: TE_MODULE; RoHS: RoHS; Temperature: -55°C+155°C; Tolerance: 1%; Voltage: NA; Wattage: 1/16W; Weight: 0.65mg; Datasheet: Y:\MIS_DATABASE\DATASHEETS\RESISTORS\CRCW0603.PDF
R126 R131 = RESISTOR: RES 10K 1/20W 1% 0201; Chkd/date: MANIRAJA/080519; Crtd /date: ALVY/080519; Custom_Duty: 15%; Customs_HS_Code: 85332119; Distributor_name: DIGIKEY; Distributor_part_number: 1276-3670-1-ND; Footprint Path: Y:\MIS_DATABASE\Library\ALTIUM_TOOL\PCB_FOOTPRINTS\Altium_Footprint_Lib.PcbLib; Height: 0.26MM; Library Path: Y:\MIS_DATABASE\Library\ALTIUM_TOOL\SCHEMATICS_PARTS\MS_DISCRETE_Library.schlib; Mfr_name: SAMSUNG; Mfr_part_number: RC0603F103CS; Mistral Part No: 110011040018-R; Package: 0201; Part #: 103158-2202R; Part_type: RESISTORS\FIXED; Project: BRUKER_SD820_COMMONDO; RoHS: RoHS; Temperature: -55°C+125°C; Tolerance: 1%; Voltage: NA; Wattage: 1/20W; Weight: 0.15mg; Datasheet: Y:\MIS_DATABASE\DATASHEETS\RESISTORS\SAMSUNG_RC-SER.PDF
R337 R343 = RESISTOR: RES 500E 1/20W 0.1% 0402; Chkd/date: MANIRAJA/190219; Crtd /date: ALVY/190219; Custom_Duty: 15%; Customs_HS_Code: 85332119; Distributor_name: DIGIKEY; Distributor_part_number: 541-1905-1-ND; Footprint Path: Y:\MIS_DATABASE\Library\ALTIUM_TOOL\PCB_FOOTPRINTS\Altium_Footprint_Lib.PcbLib; Height: 0.84MM; Library Path: Y:\MIS_DATABASE\Library\ALTIUM_TOOL\SCHEMATICS_PARTS\MS_DISCRETE_Library.schlib; Mfr_name: VISHAY; Mfr_part_number: PNM0402E5000BST1; Mistral Part No: 110019020003-R; Package: 0402; Part #: 105270-5001R; Part_type: RESISTORS\FIXED; Project: TI_J7ES_EVM_SOM; RoHS: RoHS; Temperature: -55°C+155°C; Tolerance: 0.1%; Voltage: NA; Wattage: 1/20W; Weight: NA; Datasheet: Y:\MIS_DATABASE\DATASHEETS\RESISTORS\PNM_VISHAY-SEP18.PDF
U37 = J7ES-EVM_BGA827_0: IC J7ES MICROPROCESSOR BGA827; Chkd/date: MANIRAJA/151018; Crtd /date: MANIRAJA/151018; Custom_Duty: 15%; Customs_HS_Code: 85423100; Distributor_name: NA; Distributor_part_number: NA; Footprint Path: Y:\MIS_DATABASE\Library\ALTIUM_TOOL\PCB_FOOTPRINTS\Altium_Footprint_Lib.PcbLib; Height: 2.79MM; Library Path: Y:\MIS_DATABASE\Library\ALTIUM_TOOL\SCHEMATICS_PARTS\MS_MICROPROCESSOR_Library.schlib; Library Ref: J7ES-EVM_BGA827; Mfr_name: TEXAS INSTRUMENTS; Mfr_part_number: J7ES_EVM; Mistral Part No: 141218060001; Package: BGA827; Part #: 105271-0001R-TI; Part_type: ICS\DIGITAL\MICROPROCESSOR; Project: TI_J7ES_EVM_CP; RoHS: NA; Temperature: NA; Tolerance: NA; Voltage: NA; Wattage: NA; Weight: NA; Datasheet: Y:\MIS_DATABASE\DATASHEETS\ICS\DIGITAL\MICROCONTROLLER\J7ES.PDF

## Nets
DGND: C284.2 C285.2 C292.2 C293.2 C300.2 C302.2 C362.2 C365.2 C366.2 C385.2 C521.1 C782.2 D4.1(A) Q8.1(S2) R17.1 R61.2 R74.2 R136.2 R149.2 R169.2 R190.2 R242.2 R337.2 R343.2 R348.2 U13.1(A0) U13.2(A1) U13.3(NC) U13.4(VSS) U45.3(GND) U73.B3(VSS) U73.C1(VSS) U73.E5(VSS) Y1.2(GND1) Y1.4(GND2) Y4.2(GND1) Y4.4(GND2) ; also on sheet 8 9 10 11 17 18 19 20 21 22 23 24 25 26 27 28 29 30 31 32 33 34 35 36 37 38 39 40
VBUS_USBC_CONN: R19.1 ; also on sheet 28
VDD_IO_3V3: R126.1 R131.1 R228.1 R233.1 R282.1 R288.1 ; also on sheet 10 16 18 21 25 26 27 28 29 30 31 32 34 35 36 37 38 39 40
VDD_MCUIO_1V8: C362.1 C365.1 C366.1 C782.1 R187.2 R188.2 R194.2 R195.2 R196.1 R200.1 R201.1 R203.1 R204.1 R205.1 R206.1 R207.1 R208.1 R385.2 U45.5(VCC) U73.B4(VCC) U73.D1(VCC) U73.E4(VCC) ; also on sheet 18 23
VDD_MCUIO_3V3: C521.2 R62.1 R63.1 R155.1 R158.1 R163.1 R166.1 R221.1 U13.8(VCC) ; also on sheet 18 23 24 25 26 34 37 39
A2B_MCU_SCL: U37.G27(WKUP_GPIO0_8) ; also on sheet 39
A2B_MCU_SDA: U37.G28(WKUP_GPIO0_7) ; also on sheet 39
A2B_MCU_SPI_CLK: U37.E27(MCU_SPI0_CLK) ; also on sheet 26 39
A2B_MCU_SPI_CS0: U37.E25(MCU_SPI0_CS0) ; also on sheet 39
A2B_MCU_SPI_D0: U37.E24(MCU_SPI0_D0) ; also on sheet 26 39
A2B_MCU_SPI_D1: U37.E28(MCU_SPI0_D1) ; also on sheet 26 39
A2B_SPI1_CLK: R134.2 ; also on sheet 39
A2B_SPI1_CS0: U37.W27(RGMII6_TD0) ; also on sheet 39
A2B_SPI1_D0: U37.V25(RGMII6_TD1) ; also on sheet 39
A2B_SPI1_D1: U37.W24(RGMII6_RD1) ; also on sheet 39
A2B_WKUP_GPIO_0: U37.F26(WKUP_GPIO0_0) ; also on sheet 26 39
A2B_WKUP_GPIO_1: U37.F25(WKUP_GPIO0_1) ; also on sheet 26 39
A2B_WKUP_GPIO_2: U37.F28(WKUP_GPIO0_2) ; also on sheet 26 39
A2B_WKUP_GPIO_15: U37.J27(WKUP_GPIO0_15) ; also on sheet 26 39
A2B_WKUP_UART0_RXD: RJ15.3 U37.J29(WKUP_UART0_RXD) ; also on sheet 39
A2B_WKUP_UART0_TXD: RJ14.3 U37.J28(WKUP_UART0_TXD) ; also on sheet 39
A2B_XREF_CLK_IN: R130.2 ; also on sheet 39
A2B_XREF_CLK_OUT: U37.W25(RGMII6_RD0) ; also on sheet 39
A72_CONSOLE_RXD: U37.AB2(UART0_RXD) ; also on sheet 34
A72_CONSOLE_TXD: U37.AB3(UART0_TXD) ; also on sheet 34
APL_RSTn: U37.W3(MCAN1_RX) ; also on sheet 39
AUDIO_EXT_REFCLK2: R130.1 U37.W26(RGMII6_RXC)
BOOTMODE4: U37.V6(TIMER_IO0) ; also on sheet 26
BOOTMODE5: U37.V5(TIMER_IO1) ; also on sheet 26
DP0_HPD: U37.Y4(SPI0_CS1) ; also on sheet 29
DSI_UB981_INTB: U37.AC4(UART1_CTSN) ; also on sheet 30
EMU_RSTn: R156.2 R157.2 ; also on sheet 34
ENET_INH: U37.W23(RGMII6_TD3) ; also on sheet 37
ENET_INTSn: U37.V23(RGMII6_RX_CTL) ; also on sheet 37
H_MCU_INT#: R151.2 ; also on sheet 23 24
H_MCU_PORz_1V8: TP55.1 U37.H23(MCU_PORZ) U45.2(B) ; also on sheet 23
H_MCU_SAFETY_ERRZ: R174.2 ; also on sheet 23
H_PMIC_POWER_EN1: U37.G23(PMIC_POWER_EN1) ; also on sheet 23
H_SOC_PORz_1V8: TP35.1 U37.J24(PORZ) ; also on sheet 23
I2C0_SCL: R282.2 U37.AC5(I2C0_SCL) ; also on sheet 39
I2C0_SDA: R288.2 U37.AA5(I2C0_SDA) ; also on sheet 39
I2C1_SCL: R233.2 U37.Y6(I2C1_SCL) ; also on sheet 30
I2C1_SDA: R228.2 U37.AA6(I2C1_SDA) ; also on sheet 30
I2C6_SCL: R126.2 U37.AA3(SPI0_D1) ; also on sheet 31
I2C6_SDA: R131.2 U37.W1(I3C0_SDA) ; also on sheet 31
MCAN_EN: U37.F29(WKUP_GPIO0_6) ; also on sheet 37
MCAN_nFAULT: U37.F27(WKUP_GPIO0_3) ; also on sheet 37
MCU_ADC0_AIN0: U37.K25(MCU_ADC0_AIN0) ; also on sheet 39
MCU_ADC0_AIN1: U37.K26(MCU_ADC0_AIN1) ; also on sheet 39
MCU_ADC0_AIN2: U37.K28(MCU_ADC0_AIN2) ; also on sheet 39
MCU_ADC0_AIN3: U37.L28(MCU_ADC0_AIN3) ; also on sheet 39
MCU_ADC0_AIN4: TP46.1(TP) U37.K24(MCU_ADC0_AIN4)
MCU_ADC0_AIN5: TP48.1(TP) U37.K27(MCU_ADC0_AIN5)
MCU_ADC0_AIN6: TP47.1(TP) U37.K29(MCU_ADC0_AIN6)
MCU_BOOTMODE6: U37.H29(WKUP_GPIO0_14) ; also on sheet 26
MCU_BOOTMODE8: RJ14.1 U37.G29(WKUP_GPIO0_12) ; also on sheet 26
MCU_BOOTMODE9: RJ15.1 U37.H28(WKUP_GPIO0_13) ; also on sheet 26
MCU_CAN0_STBz: U37.H26(WKUP_GPIO0_10) ; also on sheet 37
MCU_CAN1_STBz: U37.H27(WKUP_GPIO0_11) ; also on sheet 37
MCU_CONSOLE_RXD: RJ15.2 ; also on sheet 34
MCU_CONSOLE_TXD: RJ14.2 ; also on sheet 34
MCU_DMTIMER2: TP43.1(TP) U37.A28(MCU_RGMII1_TD3) ; also on sheet 22
MCU_DMTIMER3: TP6.1(TP) U37.A27(MCU_RGMII1_TD2) ; also on sheet 22
MCU_DMTIMER4: TP59.1(TP) U37.A25(MCU_RGMII1_RD3) ; also on sheet 21
MCU_DMTIMER5: TP71.1(TP) U37.D24(MCU_RGMII1_RD2) ; also on sheet 40
MCU_DMTIMER8: TP58.1(TP) U37.D26(MCU_I3C0_SCL) ; also on sheet 23
MCU_DMTIMER9: TP20.1(TP) U37.D25(MCU_I3C0_SDA) ; also on sheet 24
MCU_HYPERBUS0_CS1#: R185.1 U37.E22(MCU_OSPI1_CSN1)
MCU_HYPERBUS0_RESETO#: R186.2 U73.A2(RFU1)
MCU_I2C0_SCL: R163.2 U37.J26(MCU_I2C0_SCL) ; also on sheet 23
MCU_I2C0_SDA: R166.2 U37.H25(MCU_I2C0_SDA) ; also on sheet 23
MCU_MCAN0_RX: U37.C29(MCU_MCAN0_RX) ; also on sheet 37
MCU_MCAN0_TX: U37.D29(MCU_MCAN0_TX) ; also on sheet 37
MCU_MCAN1_RX: U37.G24(WKUP_GPIO0_5) ; also on sheet 37
MCU_MCAN1_TX: U37.G25(WKUP_GPIO0_4) ; also on sheet 37
MCU_OSPI0_CLK_N: R194.1 R378.2 U73.B1(RFU3)
MCU_OSPI0_CLK_P: R190.1 R383.2 U73.B2(C)
MCU_OSPI0_CS0#: R195.1 U37.F19(MCU_OSPI0_CSN0) U73.C2(S#)
MCU_OSPI0_D0: R206.2 U37.D20(MCU_OSPI0_D0) U73.D3(DQ0)
MCU_OSPI0_D1: R203.2 U37.G19(MCU_OSPI0_D1) U73.D2(DQ1)
MCU_OSPI0_D2: R196.2 U37.G20(MCU_OSPI0_D2) U73.C4(DQ2/W#)
MCU_OSPI0_D3: R204.2 U37.F20(MCU_OSPI0_D3) U73.D4(DQ3)
MCU_OSPI0_D4: R201.2 U37.F21(MCU_OSPI0_D4) U73.D5(DQ4)
MCU_OSPI0_D5: R205.2 U37.E21(MCU_OSPI0_D5) U73.E3(DQ5)
MCU_OSPI0_D6: R207.2 U37.B22(MCU_OSPI0_D6) U73.E2(DQ6)
MCU_OSPI0_D7: R208.2 U37.G21(MCU_OSPI0_D7) U73.E1(DQ7)
MCU_OSPI0_DQS: R197.2 R200.2 U37.D21(MCU_OSPI0_DQS)
MCU_OSPI0_ECC_FAIL: R192.1 U37.B23(MCU_OSPI1_DQS)
MCU_OSPI_RST#: U45.4(Y) U73.A4(RESET#)
MCU_PORZ_OUT: Q8.2(G2) R242.1 TP66.1 U37.B28(MCU_PORZ_OUT)
MCU_RESETSTATz: R169.1 TP51.1 U37.C27(MCU_RESETSTATZ)
MCU_RESETz: R155.2 R156.1 TP49.1 U37.D28(MCU_RESETZ)
MCUBOOT_BUFF_ENz: C385.1 Q8.6(D2) R221.2 ; also on sheet 22 34 39
MDIO0_MDC: U37.V24(MDIO0_MDC) ; also on sheet 37
MDIO0_MDIO: U37.V26(MDIO0_MDIO) ; also on sheet 37
NEO_RESETN: U37.AC2(UART0_CTSN) ; also on sheet 39
NEO_RXD: U37.AA4(UART1_RXD) ; also on sheet 39
NEO_TXD: U37.AB4(UART1_TXD) ; also on sheet 39
OSC1_XI: R141.1 U37.P29(OSC1_XI)
OSC1_XO: R143.1 U37.P27(OSC1_XO)
OSPI0_ECC_FAIL/MCU_HYPERBUS0_INT#: R187.1 R192.2 U73.A5(DNU1)
OSPI_DQS_R: R197.1 U73.C3(DQS)
PCIe0_CLKREQ#: U37.W2(I3C0_SCL) ; also on sheet 38
PWR_SW_CNTL_DSI0: U37.AB1(UART0_RTSN) ; also on sheet 40
RESET_REQz: R157.1 R158.2 TP50.1 U37.C28(RESET_REQZ)
RESETSTATz: R348.1 TP54.1 U37.T6(RESETSTATZ)
RGMII5_RD0: U37.T23(RGMII5_RD0) ; also on sheet 37
RGMII5_RD1: U37.R23(RGMII5_RD1) ; also on sheet 37
RGMII5_RD2: U37.U24(RGMII5_RD2) ; also on sheet 37
RGMII5_RD3: U37.U27(RGMII5_RD3) ; also on sheet 37
RGMII5_RX_CTL: U37.U26(RGMII5_RX_CTL) ; also on sheet 37
RGMII5_RXC: U37.U25(RGMII5_RXC) ; also on sheet 37
RGMII5_TD0: U37.U28(RGMII5_TD0) ; also on sheet 37
RGMII5_TD1: U37.V27(RGMII5_TD1) ; also on sheet 37
RGMII5_TD2: U37.V29(RGMII5_TD2) ; also on sheet 37
RGMII5_TD3: U37.V28(RGMII5_TD3) ; also on sheet 37
RGMII5_TX_CTL: U37.U23(RGMII5_TX_CTL) ; also on sheet 37
RGMII5_TXC: U37.U29(RGMII5_TXC) ; also on sheet 37
SOC_EMU0: U37.C26(EMU0) ; also on sheet 34
SOC_EMU1: U37.B29(EMU1) ; also on sheet 34
SOC_HYPERBUS0_RESET#: RJ16.3 U37.E19(MCU_OSPI0_CSN1)
SOC_MCU_OSPI0_CLK_R: R383.1 U37.E20(MCU_OSPI0_CLK)
SOC_MCU_OSPI0_LBCLKO_R: R378.1 U37.C21(MCU_OSPI0_LBCLKO)
SOC_PORZ_OUT: R136.1 U37.U1(PORZ_OUT) ; also on sheet 27 37 38
SOC_SAFETY_ERRz: R135.2 TP40.1 ; also on sheet 23
SOC_TCK: U37.E29(TCK) ; also on sheet 34
SOC_TDI: U37.V1(TDI) ; also on sheet 34
SOC_TDO: U37.V3(TDO) ; also on sheet 34
SOC_TMS: U37.V2(TMS) ; also on sheet 34
SOC_TRST#: U37.F24(TRSTN) ; also on sheet 34
SOC_WKUP_I2C0_SCL: R63.2 U13.6(SCL) U37.J25(WKUP_I2C0_SCL) ; also on sheet 23 24
SOC_WKUP_I2C0_SDA: R62.2 U13.5(SDA) U37.H24(WKUP_I2C0_SDA) ; also on sheet 23 24
SPI5_CLK: R134.1 U37.W29(RGMII6_TXC)
TUNER_INTB_CHIP0: U37.W28(RGMII6_TD2) ; also on sheet 35
TUNER_RSTB_CHIP0: U37.Y27(RGMII6_RD2) ; also on sheet 35
UB960_CAM_nPOWERON: U37.AB5(SPI0_D0) ; also on sheet 40
UB960_FRAME_SYNC: U37.AA2(SPI0_CS0) ; also on sheet 31
UB960_INTB: U37.W5(MCAN0_RX) ; also on sheet 31
UB960_PDB: U37.AA1(SPI0_CLK) ; also on sheet 31
UB981_GPIO0: U37.Y3(SPI1_CS0) ; also on sheet 30
UB981_GPIO1: U37.W4(SPI1_CS1) ; also on sheet 30
UB981_GPIO2: U37.Y5(SPI1_D0) ; also on sheet 30
UB981_GPIO3: U37.Y2(SPI1_D1) ; also on sheet 30
UB981_PDB: U37.Y1(SPI1_CLK) ; also on sheet 30
USB0_DATA_N: U37.AJ5(USB0_DM) ; also on sheet 28
USB0_DATA_P: U37.AH6(USB0_DP) ; also on sheet 28
USB0_DRVVBUS: U37.U6(USB0_DRVVBUS) ; also on sheet 28
USB0_ID: U37.AC6(USB0_ID) ; also on sheet 28
USB0_IMON: U37.L29(MCU_ADC0_AIN7) ; also on sheet 28
USB0_RCALIB: R343.1 U37.AB6(USB0_RCALIB)
USB0_STATUS: U37.AD5(UART1_RTSN) ; also on sheet 28
USB0_VBUS_OCN: U37.W6(MCAN0_TX) ; also on sheet 28
USB0_VBUS_SOC: R17.2 R18.2 U37.AC7(USB0_VBUS)
USB1_DATA_N: U37.AH7(USB1_DM) ; also on sheet 38
USB1_DATA_P: U37.AJ6(USB1_DP) ; also on sheet 38
USB1_DRVVBUS: R71.1 U37.V4(MCAN1_TX) ; also on sheet 38
USB1_ID: U37.AD7(USB1_ID) ; also on sheet 28
USB1_RCALIB: R337.1 U37.AD9(USB1_RCALIB)
USB1_VBUS_SOC: R71.2 R74.1 U37.AD8(USB1_VBUS)
WKUP_GPIO0_30: R186.1 RJ16.1 U37.A23(MCU_OSPI1_LBCLKO)
WKUP_LFOSC_XI: R146.1 U37.N28(WKUP_LFOSC0_XI)
WKUP_LFOSC_XO: R147.1 U37.N26(WKUP_LFOSC0_XO)
WKUP_OSC0_XIN: C300.1 U37.M29(WKUP_OSC0_XI) Y4.3
WKUP_OSC0_XOUT: C302.1 U37.M27(WKUP_OSC0_XO) Y4.1
N23139394: D4.3(C) R18.1 R19.2
N23154802: R174.1 U37.D27(MCU_SAFETY_ERRORN)
N24377130: R135.1 U37.U4(SOC_SAFETY_ERRORN)
N24525426: R151.1 U37.G26(WKUP_GPIO0_9)
N28200806: C293.1 R146.2 Y2.2
N28200825: C292.1 R147.2 Y2.1
N28200987: C284.1 R141.2 Y1.3
N28201033: C285.1 R143.2 Y1.1
N28998069: TP57.1(TP) U37.F13(TEMP_DIODE_P)
N29500308: R149.1 U37.L24(MCU_ADC1_AIN2) U37.L25(MCU_ADC1_AIN6) U37.L26(MCU_ADC1_AIN3) U37.L27(MCU_ADC1_AIN7) U37.M24(MCU_ADC1_AIN5) U37.M25(MCU_ADC1_AIN1) U37.N23(MCU_ADC1_AIN0) U37.N24(MCU_ADC1_AIN4)
N30186501: R385.1 RJ16.2 U45.1(A)
N32137181: R185.2 R188.1 U73.A3(RFU2)
N32413216: R61.1 TP15.1(TP) U13.7(WP)

Not connected (* = marked no-connect by the designer): D4 2(NC)*; U37 A24(MCU_RGMII1_RD1) A26(MCU_RGMII1_TD1) AJ29(ATEST0)* B24(MCU_RGMII1_RD0) B25(MCU_RGMII1_TD0) B26(MCU_RGMII1_TXC) B27(MCU_RGMII1_TX_CTL) C22(MCU_OSPI1_CSN0) C23(MCU_OSPI1_D3) C24(MCU_RGMII1_RXC) C25(MCU_RGMII1_RX_CTL) D22(MCU_OSPI1_D0) D23(MCU_OSPI1_D2) E23(MCU_MDIO0_MDIO) E26(PMIC_POWER_EN0) F22(MCU_OSPI1_CLK) F23(MCU_MDIO0_MDC) G22(MCU_OSPI1_D1) N25(MAIN_ATEST)* P26(IFORCE)* R27(VSENSE)* U2(ECAP0_IN_APWM_OUT) U3(EXT_REFCLK1) Y28(RGMII6_TX_CTL) Y29(RGMII6_RD3); U73 B5(DNU2)* C5(VPP)*

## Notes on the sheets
sheet 12
- MCU FLASH
- Route SOC_MCU_OSPI0_CLK
  & SOC_MCU_OSPI0_LBCLKO
  as differential pair
- REV A1: NO-POP FOR OSPI
- OSPI FLASH RESET
- OSPI  FLASH
- HYPERBUS CKn, OSPI LBCLK
sheet 13
- MCU_RGMII
- MCU ADCs
- MAIN RGMII
sheet 14
- MCU & MAIN GENERAL IO, OSC CLKS
- MCU DUAL PURPOSE PINS. A2B CANNOT
  DRIVE UNTIL AFTER RESET
- SOC_WARMRESET#
- [MCU Warm Reset In]
- DISABLE DRIVERS TIED TO BOOT PINS DURING BOOT.
- BOARD ID EEPROM
- OSC
- CLKS
sheet 15
- GENERAL
- USB
- USB VBUS Resistor divider circuit
- Note: Recommended VBUS circuit for USB connector. Supports 5V-30V VBUS
- Note: Recommended VBUS circuit for embedded Hub
